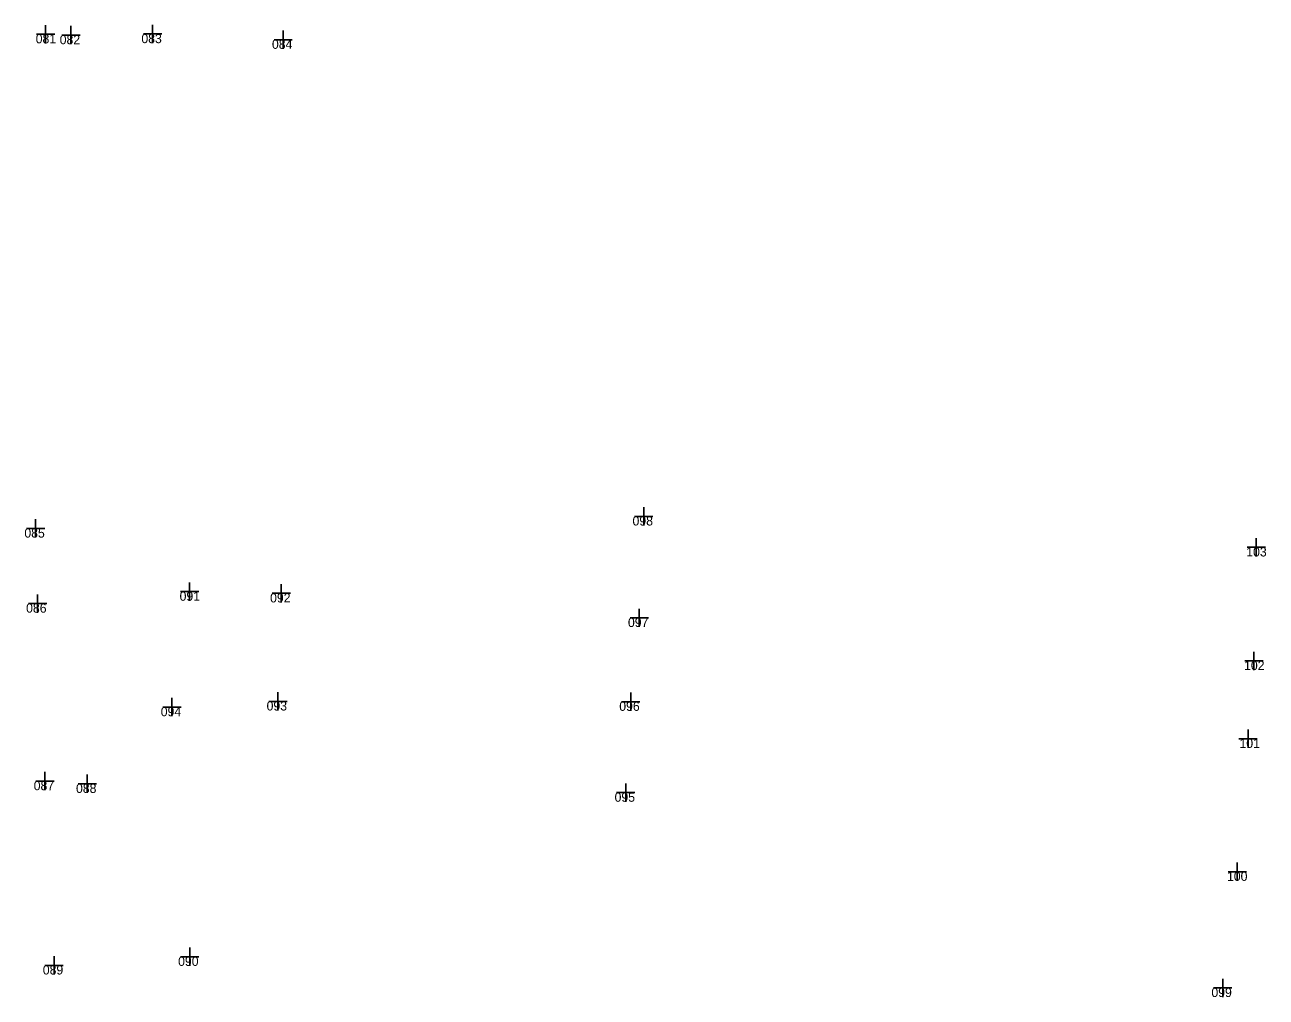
# Model space of a CAD drawing. Extents: x -706655 to -706193, y -1036183 to -1035040.
# Drawn here: x -706407.8 to -706340.1, y -1035526.2 to -1035473.1 of the extents above; entities that cross this region are included whole.
import ezdxf

# ---------------------------------------------------------------- set-up
doc = ezdxf.new("R2010")
doc.units = 0
doc.layers.add('čísla bodu', color=7, linetype='Continuous')

msp = doc.modelspace()

# ---------------------------------------------------------------- linework, layer by layer
at = {"layer": 'čísla bodu'}
for p, q in [((-706406.71, -1035474.12), (-706406.71, -1035473.12)), ((-706405.33, -1035474.17), (-706405.33, -1035473.17)), ((-706400.87, -1035474.11), (-706400.87, -1035473.11)), ((-706393.74, -1035474.42), (-706393.74, -1035473.42)), ((-706407.21, -1035473.62), (-706406.21, -1035473.62)), ((-706406.71, -1035473.62), (-706406.71, -1035473.62)), ((-706405.83, -1035473.67), (-706404.83, -1035473.67)), ((-706405.33, -1035473.67), (-706405.33, -1035473.67)), ((-706401.37, -1035473.61), (-706400.37, -1035473.61)), ((-706400.87, -1035473.61), (-706400.87, -1035473.61)), ((-706394.24, -1035473.92), (-706393.24, -1035473.92)), ((-706393.74, -1035473.92), (-706393.74, -1035473.92)), ((-706374.55, -1035499.94), (-706373.55, -1035499.94)), ((-706374.05, -1035500.44), (-706374.05, -1035499.44)), ((-706374.05, -1035499.94), (-706374.05, -1035499.94)), ((-706407.76, -1035500.6), (-706406.76, -1035500.6)), ((-706407.26, -1035501.1), (-706407.26, -1035500.1)), ((-706407.26, -1035500.6), (-706407.26, -1035500.6)), ((-706340.61, -1035502.13), (-706340.61, -1035501.13)), ((-706341.11, -1035501.63), (-706340.11, -1035501.63)), ((-706340.61, -1035501.63), (-706340.61, -1035501.63)), ((-706398.85, -1035504.55), (-706398.85, -1035503.55)), ((-706393.84, -1035504.64), (-706393.84, -1035503.64)), ((-706407.15, -1035505.2), (-706407.15, -1035504.2)), ((-706399.35, -1035504.05), (-706398.35, -1035504.05)), ((-706398.85, -1035504.05), (-706398.85, -1035504.05)), ((-706394.34, -1035504.14), (-706393.34, -1035504.14)), ((-706393.84, -1035504.14), (-706393.84, -1035504.14)), ((-706407.65, -1035504.7), (-706406.65, -1035504.7)), ((-706407.15, -1035504.7), (-706407.15, -1035504.7)), ((-706374.3, -1035505.98), (-706374.3, -1035504.98)), ((-706374.8, -1035505.48), (-706373.8, -1035505.48)), ((-706374.3, -1035505.48), (-706374.3, -1035505.48)), ((-706340.73, -1035508.33), (-706340.73, -1035507.33)), ((-706341.23, -1035507.83), (-706340.23, -1035507.83)), ((-706340.73, -1035507.83), (-706340.73, -1035507.83)), ((-706399.81, -1035510.85), (-706399.81, -1035509.85)), ((-706394.53, -1035510.04), (-706393.53, -1035510.04)), ((-706394.03, -1035510.54), (-706394.03, -1035509.54)), ((-706394.03, -1035510.04), (-706394.03, -1035510.04)), ((-706375.26, -1035510.06), (-706374.26, -1035510.06)), ((-706374.76, -1035510.56), (-706374.76, -1035509.56)), ((-706374.76, -1035510.06), (-706374.76, -1035510.06)), ((-706400.31, -1035510.35), (-706399.31, -1035510.35)), ((-706399.81, -1035510.35), (-706399.81, -1035510.35)), ((-706341.55, -1035512.08), (-706340.55, -1035512.08)), ((-706341.05, -1035512.58), (-706341.05, -1035511.58)), ((-706341.05, -1035512.08), (-706341.05, -1035512.08)), ((-706406.75, -1035514.89), (-706406.75, -1035513.89)), ((-706404.44, -1035515.04), (-706404.44, -1035514.04)), ((-706407.25, -1035514.39), (-706406.25, -1035514.39)), ((-706406.75, -1035514.39), (-706406.75, -1035514.39)), ((-706404.94, -1035514.54), (-706403.94, -1035514.54)), ((-706404.44, -1035514.54), (-706404.44, -1035514.54)), ((-706375.03, -1035515.52), (-706375.03, -1035514.52)), ((-706375.53, -1035515.02), (-706374.53, -1035515.02)), ((-706375.03, -1035515.02), (-706375.03, -1035515.02)), ((-706341.64, -1035519.84), (-706341.64, -1035518.84)), ((-706342.14, -1035519.34), (-706341.14, -1035519.34)), ((-706341.64, -1035519.34), (-706341.64, -1035519.34)), ((-706398.84, -1035524.48), (-706398.84, -1035523.48)), ((-706406.25, -1035524.95), (-706406.25, -1035523.95)), ((-706399.34, -1035523.98), (-706398.34, -1035523.98)), ((-706398.84, -1035523.98), (-706398.84, -1035523.98)), ((-706406.75, -1035524.45), (-706405.75, -1035524.45)), ((-706406.25, -1035524.45), (-706406.25, -1035524.45)), ((-706342.94, -1035525.68), (-706341.94, -1035525.68)), ((-706342.44, -1035526.18), (-706342.44, -1035525.18)), ((-706342.44, -1035525.68), (-706342.44, -1035525.68))]:
    msp.add_line(p, q, dxfattribs=at)

# ---------------------------------------------------------------- texts
for s, p in [('081', (-706407.252, -1035474.12)), ('082', (-706405.942, -1035474.17)), ('083', (-706401.482, -1035474.11)), ('084', (-706394.352, -1035474.42)), ('098', (-706374.664, -1035500.44)), ('085', (-706407.872, -1035501.1)), ('103', (-706341.151, -1035502.13)), ('086', (-706407.776, -1035505.2)), ('091', (-706399.394, -1035504.55)), ('092', (-706394.454, -1035504.64)), ('097', (-706374.914, -1035505.98)), ('102', (-706341.271, -1035508.33)), ('093', (-706394.644, -1035510.54)), ('096', (-706375.388, -1035510.56)), ('094', (-706400.424, -1035510.85)), ('101', (-706341.522, -1035512.58)), ('087', (-706407.362, -1035514.89)), ('088', (-706405.052, -1035515.04)), ('095', (-706375.644, -1035515.52)), ('100', (-706342.203, -1035519.84)), ('090', (-706399.476, -1035524.48)), ('089', (-706406.864, -1035524.95)), ('099', (-706343.056, -1035526.18))]:
    msp.add_text(s, height=0.5, dxfattribs=at).set_placement(p)

doc.saveas('drawing.dxf')
